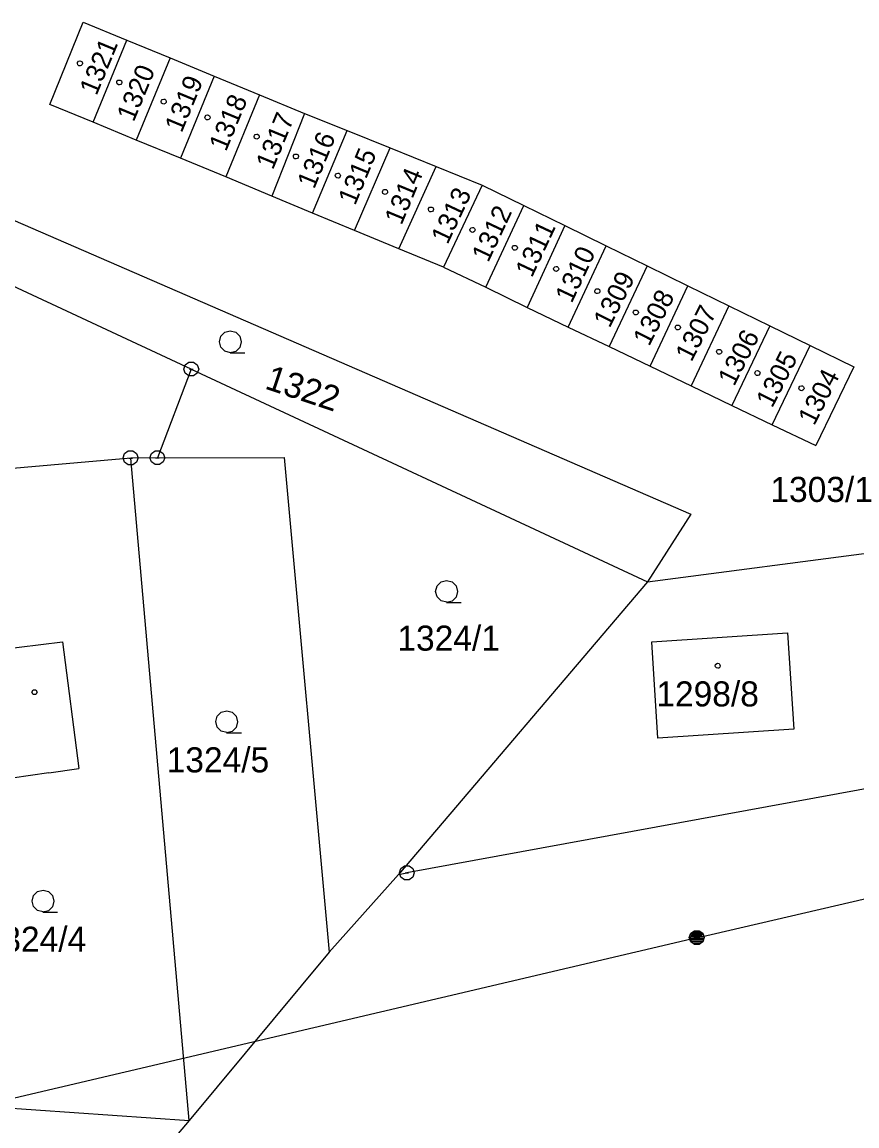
# Model space of a CAD drawing. Extents: x -806774 to -803680, y -1151731 to -1150053.
# Drawn here: x -804567.4 to -804510.8, y -1150464.6 to -1150389.8 of the extents above; entities that cross this region are included whole.
import ezdxf

# ---------------------------------------------------------------- set-up
doc = ezdxf.new("R2010")
doc.units = 0
for name, color, linetype in [('1', 7, 'Continuous'), ('12', 7, 'Continuous'), ('2', 7, 'Continuous'), ('3', 7, 'Continuous'), ('5', 7, 'Continuous'), ('6', 7, 'Continuous'), ('8', 7, 'Continuous')]:
    doc.layers.add(name, color=color, linetype=linetype)

msp = doc.modelspace()

# ---------------------------------------------------------------- linework, layer by layer
at = {"layer": '1'}
for p, q in [((-804565.48, -1150395.39), (-804563.21, -1150389.81)), ((-804563.21, -1150389.81), (-804560.24, -1150391.03)), ((-804562.53, -1150396.6), (-804560.24, -1150391.03)), ((-804560.24, -1150391.03), (-804557.32, -1150392.24)), ((-804557.32, -1150392.24), (-804559.61, -1150397.81)), ((-804557.32, -1150392.24), (-804554.33, -1150393.48)), ((-804554.33, -1150393.48), (-804556.62, -1150399.04)), ((-804554.33, -1150393.48), (-804551.25, -1150394.75)), ((-804562.53, -1150396.6), (-804565.48, -1150395.39)), ((-804551.25, -1150394.75), (-804553.54, -1150400.31)), ((-804551.25, -1150394.75), (-804548.2, -1150396)), ((-804548.2, -1150396), (-804550.43, -1150401.62)), ((-804548.2, -1150396), (-804545.32, -1150397.16)), ((-804559.61, -1150397.81), (-804562.53, -1150396.6)), ((-804547.66, -1150402.76), (-804545.32, -1150397.16)), ((-804545.32, -1150397.16), (-804542.4, -1150398.34)), ((-804556.62, -1150399.04), (-804559.61, -1150397.81)), ((-804544.83, -1150403.93), (-804542.4, -1150398.34)), ((-804542.4, -1150398.34), (-804539.29, -1150399.6)), ((-804553.54, -1150400.31), (-804556.62, -1150399.04)), ((-804541.82, -1150405.18), (-804539.29, -1150399.6)), ((-804539.29, -1150399.6), (-804536.16, -1150400.86)), ((-804574.73, -1150400.29), (-804522.03, -1150423.17)), ((-804550.43, -1150401.62), (-804553.54, -1150400.31)), ((-804536.16, -1150400.86), (-804538.78, -1150406.43)), ((-804536.16, -1150400.86), (-804533.35, -1150402.24)), ((-804547.66, -1150402.76), (-804550.43, -1150401.62)), ((-804544.83, -1150403.93), (-804547.66, -1150402.76)), ((-804535.93, -1150407.79), (-804533.35, -1150402.24)), ((-804533.35, -1150402.24), (-804530.56, -1150403.6)), ((-804530.56, -1150403.6), (-804533.11, -1150409.15)), ((-804530.56, -1150403.6), (-804527.76, -1150404.97)), ((-804555.88, -1150413.34), (-804576.01, -1150403.97)), ((-804541.82, -1150405.18), (-804544.83, -1150403.93)), ((-804538.78, -1150406.43), (-804541.82, -1150405.18)), ((-804530.34, -1150410.48), (-804527.76, -1150404.97)), ((-804527.76, -1150404.97), (-804524.99, -1150406.33)), ((-804538.78, -1150406.43), (-804535.93, -1150407.79)), ((-804524.99, -1150406.33), (-804527.56, -1150411.81)), ((-804524.99, -1150406.33), (-804522.22, -1150407.69)), ((-804535.93, -1150407.79), (-804533.11, -1150409.15)), ((-804524.79, -1150413.14), (-804522.22, -1150407.69)), ((-804522.22, -1150407.69), (-804519.45, -1150409.04)), ((-804533.11, -1150409.15), (-804530.34, -1150410.48)), ((-804519.45, -1150409.04), (-804522.01, -1150414.47)), ((-804519.45, -1150409.04), (-804516.67, -1150410.4)), ((-804516.67, -1150410.4), (-804519.24, -1150415.8)), ((-804516.67, -1150410.4), (-804513.94, -1150411.74)), ((-804530.34, -1150410.48), (-804527.56, -1150411.81)), ((-804527.56, -1150411.81), (-804524.79, -1150413.14)), ((-804516.51, -1150417.1), (-804513.94, -1150411.74)), ((-804513.94, -1150411.74), (-804510.98, -1150413.19)), ((-804555.88, -1150413.34), (-804558.18, -1150419.35)), ((-804555.88, -1150413.34), (-804524.97, -1150427.75)), ((-804524.79, -1150413.14), (-804522.01, -1150414.47)), ((-804510.98, -1150413.19), (-804513.55, -1150418.52)), ((-804522.01, -1150414.47), (-804519.24, -1150415.8)), ((-804519.24, -1150415.8), (-804516.51, -1150417.1)), ((-804516.51, -1150417.1), (-804513.55, -1150418.52)), ((-804559.99, -1150419.36), (-804578.84, -1150421.02)), ((-804558.18, -1150419.35), (-804559.99, -1150419.36)), ((-804556.02, -1150464.26), (-804559.99, -1150419.36)), ((-804558.18, -1150419.35), (-804549.59, -1150419.33)), ((-804549.59, -1150419.33), (-804546.53, -1150452.86)), ((-804522.03, -1150423.17), (-804524.97, -1150427.75)), ((-804524.97, -1150427.75), (-804507.58, -1150425.47)), ((-804524.97, -1150427.75), (-804541.85, -1150447.6)), ((-804524.68, -1150431.81), (-804515.47, -1150431.2)), ((-804515.47, -1150431.2), (-804515.04, -1150437.73)), ((-804569.15, -1150432.37), (-804564.6, -1150431.82)), ((-804564.6, -1150431.82), (-804563.5, -1150440.4)), ((-804457.42, -1150432.08), (-804541.27, -1150447.49)), ((-804524.27, -1150438.36), (-804524.68, -1150431.81)), ((-804515.04, -1150437.73), (-804524.27, -1150438.36)), ((-804565.54, -1150440.7), (-804568.02, -1150441.07)), ((-804565.54, -1150440.7), (-804563.5, -1150440.4)), ((-804541.85, -1150447.6), (-804546.53, -1150452.86)), ((-804541.85, -1150447.6), (-804541.27, -1150447.49)), ((-804546.53, -1150452.86), (-804556.02, -1150464.26)), ((-804575.03, -1150462.95), (-804556.02, -1150464.26)), ((-804556.02, -1150464.26), (-804563.32, -1150472.84))]:
    msp.add_line(p, q, dxfattribs=at)
at = {"layer": '12'}
for p, q in [((-804565.48, -1150395.39), (-804563.21, -1150389.81)), ((-804563.21, -1150389.81), (-804560.24, -1150391.03)), ((-804562.53, -1150396.6), (-804560.24, -1150391.03)), ((-804562.53, -1150396.6), (-804560.24, -1150391.03)), ((-804560.24, -1150391.03), (-804557.32, -1150392.24)), ((-804557.32, -1150392.24), (-804559.61, -1150397.81)), ((-804557.32, -1150392.24), (-804559.61, -1150397.81)), ((-804557.32, -1150392.24), (-804554.33, -1150393.48)), ((-804554.33, -1150393.48), (-804556.62, -1150399.04)), ((-804554.33, -1150393.48), (-804556.62, -1150399.04)), ((-804554.33, -1150393.48), (-804551.25, -1150394.75)), ((-804562.53, -1150396.6), (-804565.48, -1150395.39)), ((-804551.25, -1150394.75), (-804553.54, -1150400.31)), ((-804551.25, -1150394.75), (-804553.54, -1150400.31)), ((-804551.25, -1150394.75), (-804548.2, -1150396)), ((-804548.2, -1150396), (-804550.43, -1150401.62)), ((-804548.2, -1150396), (-804550.43, -1150401.62)), ((-804548.2, -1150396), (-804545.32, -1150397.16)), ((-804559.61, -1150397.81), (-804562.53, -1150396.6)), ((-804547.66, -1150402.76), (-804545.32, -1150397.16)), ((-804547.66, -1150402.76), (-804545.32, -1150397.16)), ((-804545.32, -1150397.16), (-804542.4, -1150398.34)), ((-804556.62, -1150399.04), (-804559.61, -1150397.81)), ((-804544.83, -1150403.93), (-804542.4, -1150398.34)), ((-804544.83, -1150403.93), (-804542.4, -1150398.34)), ((-804542.4, -1150398.34), (-804539.29, -1150399.6)), ((-804553.54, -1150400.31), (-804556.62, -1150399.04)), ((-804541.82, -1150405.18), (-804539.29, -1150399.6)), ((-804541.82, -1150405.18), (-804539.29, -1150399.6)), ((-804539.29, -1150399.6), (-804536.16, -1150400.86)), ((-804550.43, -1150401.62), (-804553.54, -1150400.31)), ((-804536.16, -1150400.86), (-804538.78, -1150406.43)), ((-804536.16, -1150400.86), (-804538.78, -1150406.43)), ((-804536.16, -1150400.86), (-804533.35, -1150402.24)), ((-804547.66, -1150402.76), (-804550.43, -1150401.62)), ((-804544.83, -1150403.93), (-804547.66, -1150402.76)), ((-804535.93, -1150407.79), (-804533.35, -1150402.24)), ((-804535.93, -1150407.79), (-804533.35, -1150402.24)), ((-804533.35, -1150402.24), (-804530.56, -1150403.6)), ((-804530.56, -1150403.6), (-804533.11, -1150409.15)), ((-804530.56, -1150403.6), (-804533.11, -1150409.15)), ((-804530.56, -1150403.6), (-804527.76, -1150404.97)), ((-804541.82, -1150405.18), (-804544.83, -1150403.93)), ((-804538.78, -1150406.43), (-804541.82, -1150405.18)), ((-804530.34, -1150410.48), (-804527.76, -1150404.97)), ((-804530.34, -1150410.48), (-804527.76, -1150404.97)), ((-804527.76, -1150404.97), (-804524.99, -1150406.33)), ((-804538.78, -1150406.43), (-804535.93, -1150407.79)), ((-804524.99, -1150406.33), (-804527.56, -1150411.81)), ((-804524.99, -1150406.33), (-804527.56, -1150411.81)), ((-804524.99, -1150406.33), (-804522.22, -1150407.69)), ((-804535.93, -1150407.79), (-804533.11, -1150409.15)), ((-804524.79, -1150413.14), (-804522.22, -1150407.69)), ((-804524.79, -1150413.14), (-804522.22, -1150407.69)), ((-804522.22, -1150407.69), (-804519.45, -1150409.04)), ((-804533.11, -1150409.15), (-804530.34, -1150410.48)), ((-804519.45, -1150409.04), (-804522.01, -1150414.47)), ((-804519.45, -1150409.04), (-804522.01, -1150414.47)), ((-804519.45, -1150409.04), (-804516.67, -1150410.4)), ((-804516.67, -1150410.4), (-804519.24, -1150415.8)), ((-804516.67, -1150410.4), (-804519.24, -1150415.8)), ((-804516.67, -1150410.4), (-804513.94, -1150411.74)), ((-804530.34, -1150410.48), (-804527.56, -1150411.81)), ((-804527.56, -1150411.81), (-804524.79, -1150413.14)), ((-804516.51, -1150417.1), (-804513.94, -1150411.74)), ((-804516.51, -1150417.1), (-804513.94, -1150411.74)), ((-804513.94, -1150411.74), (-804510.98, -1150413.19)), ((-804524.79, -1150413.14), (-804522.01, -1150414.47)), ((-804510.98, -1150413.19), (-804513.55, -1150418.52)), ((-804522.01, -1150414.47), (-804519.24, -1150415.8)), ((-804519.24, -1150415.8), (-804516.51, -1150417.1)), ((-804516.51, -1150417.1), (-804513.55, -1150418.52)), ((-804524.68, -1150431.81), (-804515.47, -1150431.2)), ((-804515.47, -1150431.2), (-804515.04, -1150437.73)), ((-804524.27, -1150438.36), (-804524.68, -1150431.81)), ((-804515.04, -1150437.73), (-804524.27, -1150438.36))]:
    msp.add_line(p, q, dxfattribs=at)
at = {"layer": '3'}
for points in [[(-804553.23, -1150412.22), (-804553.61, -1150412.12), (-804553.88, -1150411.85), (-804553.98, -1150411.48), (-804553.88, -1150411.11), (-804553.61, -1150410.84), (-804553.24, -1150410.74), (-804552.87, -1150410.84), (-804552.6, -1150411.11), (-804552.5, -1150411.49), (-804552.6, -1150411.87), (-804552.87, -1150412.14), (-804553.25, -1150412.24), (-804552.25, -1150412.24)], [(-804538.57, -1150429.14), (-804538.95, -1150429.04), (-804539.22, -1150428.77), (-804539.32, -1150428.4), (-804539.22, -1150428.03), (-804538.95, -1150427.76), (-804538.58, -1150427.66), (-804538.21, -1150427.76), (-804537.94, -1150428.03), (-804537.84, -1150428.41), (-804537.94, -1150428.79), (-804538.21, -1150429.06), (-804538.59, -1150429.16), (-804537.59, -1150429.16)], [(-804553.47, -1150437.97), (-804553.85, -1150437.87), (-804554.12, -1150437.6), (-804554.22, -1150437.23), (-804554.12, -1150436.86), (-804553.85, -1150436.59), (-804553.48, -1150436.49), (-804553.11, -1150436.59), (-804552.84, -1150436.86), (-804552.74, -1150437.24), (-804552.84, -1150437.62), (-804553.11, -1150437.89), (-804553.49, -1150437.99), (-804552.49, -1150437.99)], [(-804565.92, -1150450.13), (-804566.3, -1150450.03), (-804566.57, -1150449.76), (-804566.67, -1150449.39), (-804566.57, -1150449.02), (-804566.3, -1150448.75), (-804565.93, -1150448.65), (-804565.56, -1150448.75), (-804565.29, -1150449.02), (-804565.19, -1150449.4), (-804565.29, -1150449.78), (-804565.56, -1150450.05), (-804565.94, -1150450.15), (-804564.94, -1150450.15)]]:
    msp.add_lwpolyline(points, dxfattribs=at)
at = {"layer": '5'}
for points in [[(-804563.587, -1150392.545), (-804563.53, -1150392.46), (-804563.428, -1150392.448), (-804563.365, -1150392.453), (-804563.289, -1150392.506), (-804563.255, -1150392.607), (-804563.273, -1150392.675), (-804563.335, -1150392.747), (-804563.414, -1150392.779), (-804563.495, -1150392.767), (-804563.571, -1150392.714), (-804563.605, -1150392.613)], [(-804560.917, -1150393.835), (-804560.86, -1150393.75), (-804560.758, -1150393.738), (-804560.695, -1150393.743), (-804560.619, -1150393.796), (-804560.585, -1150393.897), (-804560.603, -1150393.965), (-804560.665, -1150394.037), (-804560.744, -1150394.069), (-804560.825, -1150394.057), (-804560.901, -1150394.004), (-804560.935, -1150393.903)], [(-804557.907, -1150395.135), (-804557.85, -1150395.05), (-804557.748, -1150395.038), (-804557.685, -1150395.043), (-804557.609, -1150395.096), (-804557.575, -1150395.197), (-804557.593, -1150395.265), (-804557.655, -1150395.337), (-804557.734, -1150395.369), (-804557.815, -1150395.357), (-804557.891, -1150395.304), (-804557.925, -1150395.203)], [(-804554.937, -1150396.205), (-804554.88, -1150396.12), (-804554.778, -1150396.108), (-804554.715, -1150396.113), (-804554.639, -1150396.166), (-804554.605, -1150396.267), (-804554.623, -1150396.335), (-804554.685, -1150396.407), (-804554.764, -1150396.439), (-804554.845, -1150396.427), (-804554.921, -1150396.374), (-804554.955, -1150396.273)], [(-804551.607, -1150397.505), (-804551.55, -1150397.42), (-804551.448, -1150397.408), (-804551.385, -1150397.413), (-804551.309, -1150397.466), (-804551.275, -1150397.567), (-804551.293, -1150397.635), (-804551.355, -1150397.707), (-804551.434, -1150397.739), (-804551.515, -1150397.727), (-804551.591, -1150397.674), (-804551.625, -1150397.573)], [(-804548.947, -1150398.855), (-804548.89, -1150398.77), (-804548.788, -1150398.758), (-804548.725, -1150398.763), (-804548.649, -1150398.816), (-804548.615, -1150398.917), (-804548.633, -1150398.985), (-804548.695, -1150399.057), (-804548.774, -1150399.089), (-804548.855, -1150399.077), (-804548.931, -1150399.024), (-804548.965, -1150398.923)], [(-804546.107, -1150400.155), (-804546.05, -1150400.07), (-804545.948, -1150400.058), (-804545.885, -1150400.063), (-804545.809, -1150400.116), (-804545.775, -1150400.217), (-804545.793, -1150400.285), (-804545.855, -1150400.357), (-804545.934, -1150400.389), (-804546.015, -1150400.377), (-804546.091, -1150400.324), (-804546.125, -1150400.223)], [(-804542.907, -1150401.255), (-804542.85, -1150401.17), (-804542.748, -1150401.158), (-804542.685, -1150401.163), (-804542.609, -1150401.216), (-804542.575, -1150401.317), (-804542.593, -1150401.385), (-804542.655, -1150401.457), (-804542.734, -1150401.489), (-804542.815, -1150401.477), (-804542.891, -1150401.424), (-804542.925, -1150401.323)], [(-804539.797, -1150402.445), (-804539.74, -1150402.36), (-804539.638, -1150402.348), (-804539.575, -1150402.353), (-804539.499, -1150402.406), (-804539.465, -1150402.507), (-804539.483, -1150402.575), (-804539.545, -1150402.647), (-804539.624, -1150402.679), (-804539.705, -1150402.667), (-804539.781, -1150402.614), (-804539.815, -1150402.513)], [(-804536.977, -1150403.835), (-804536.92, -1150403.75), (-804536.818, -1150403.738), (-804536.755, -1150403.743), (-804536.679, -1150403.796), (-804536.645, -1150403.897), (-804536.663, -1150403.965), (-804536.725, -1150404.037), (-804536.804, -1150404.069), (-804536.885, -1150404.057), (-804536.961, -1150404.004), (-804536.995, -1150403.903)], [(-804534.107, -1150405.045), (-804534.05, -1150404.96), (-804533.948, -1150404.948), (-804533.885, -1150404.953), (-804533.809, -1150405.006), (-804533.775, -1150405.107), (-804533.793, -1150405.175), (-804533.855, -1150405.247), (-804533.934, -1150405.279), (-804534.015, -1150405.267), (-804534.091, -1150405.214), (-804534.125, -1150405.113)], [(-804531.307, -1150406.475), (-804531.25, -1150406.39), (-804531.148, -1150406.378), (-804531.085, -1150406.383), (-804531.009, -1150406.436), (-804530.975, -1150406.537), (-804530.993, -1150406.605), (-804531.055, -1150406.677), (-804531.134, -1150406.709), (-804531.215, -1150406.697), (-804531.291, -1150406.644), (-804531.325, -1150406.543)], [(-804528.517, -1150407.985), (-804528.46, -1150407.9), (-804528.358, -1150407.888), (-804528.295, -1150407.893), (-804528.219, -1150407.946), (-804528.185, -1150408.047), (-804528.203, -1150408.115), (-804528.265, -1150408.187), (-804528.344, -1150408.219), (-804528.425, -1150408.207), (-804528.501, -1150408.154), (-804528.535, -1150408.053)], [(-804525.907, -1150409.425), (-804525.85, -1150409.34), (-804525.748, -1150409.328), (-804525.685, -1150409.333), (-804525.609, -1150409.386), (-804525.575, -1150409.487), (-804525.593, -1150409.555), (-804525.655, -1150409.627), (-804525.734, -1150409.659), (-804525.815, -1150409.647), (-804525.891, -1150409.594), (-804525.925, -1150409.493)], [(-804523.067, -1150410.445), (-804523.01, -1150410.36), (-804522.908, -1150410.348), (-804522.845, -1150410.353), (-804522.769, -1150410.406), (-804522.735, -1150410.507), (-804522.753, -1150410.575), (-804522.815, -1150410.647), (-804522.894, -1150410.679), (-804522.975, -1150410.667), (-804523.051, -1150410.614), (-804523.085, -1150410.513)], [(-804520.267, -1150412.095), (-804520.21, -1150412.01), (-804520.108, -1150411.998), (-804520.045, -1150412.003), (-804519.969, -1150412.056), (-804519.935, -1150412.157), (-804519.953, -1150412.225), (-804520.015, -1150412.297), (-804520.094, -1150412.329), (-804520.175, -1150412.317), (-804520.251, -1150412.264), (-804520.285, -1150412.163)], [(-804517.667, -1150413.535), (-804517.61, -1150413.45), (-804517.508, -1150413.438), (-804517.445, -1150413.443), (-804517.369, -1150413.496), (-804517.335, -1150413.597), (-804517.353, -1150413.665), (-804517.415, -1150413.737), (-804517.494, -1150413.769), (-804517.575, -1150413.757), (-804517.651, -1150413.704), (-804517.685, -1150413.603)], [(-804514.687, -1150414.565), (-804514.63, -1150414.48), (-804514.528, -1150414.468), (-804514.465, -1150414.473), (-804514.389, -1150414.526), (-804514.355, -1150414.627), (-804514.373, -1150414.695), (-804514.435, -1150414.767), (-804514.514, -1150414.799), (-804514.595, -1150414.787), (-804514.671, -1150414.734), (-804514.705, -1150414.633)], [(-804520.2, -1150433.27), (-804520.1, -1150433.29), (-804520.05, -1150433.38), (-804520.03, -1150433.44), (-804520.05, -1150433.53), (-804520.13, -1150433.6), (-804520.2, -1150433.61), (-804520.29, -1150433.58), (-804520.35, -1150433.52), (-804520.37, -1150433.44), (-804520.35, -1150433.35), (-804520.27, -1150433.28)], [(-804566.41, -1150435.08), (-804566.32, -1150435.23), (-804566.41, -1150435.38), (-804566.59, -1150435.38), (-804566.68, -1150435.23), (-804566.59, -1150435.08)]]:
    msp.add_lwpolyline(points, close=True, dxfattribs=at)
at = {"layer": '6'}
for q in [(-804453.4, -1150436.09), (-804579.51, -1150465.49)]:
    msp.add_line((-804521.63, -1150451.88), q, dxfattribs=at)
msp.add_lwpolyline([(-804521.78, -1150451.4), (-804521.47, -1150451.4), (-804521.22, -1150451.58), (-804521.12, -1150451.87), (-804521.22, -1150452.16), (-804521.47, -1150452.34), (-804521.78, -1150452.34), (-804522.03, -1150452.16), (-804522.13, -1150451.87), (-804522.03, -1150451.58), (-804521.78, -1150451.4), (-804521.75, -1150451.44), (-804521.51, -1150451.44), (-804521.35, -1150451.52), (-804521.91, -1150451.52), (-804521.99, -1150451.6), (-804521.27, -1150451.6), (-804521.27, -1150451.68), (-804521.99, -1150451.68), (-804522.03, -1150451.76), (-804521.23, -1150451.76), (-804521.19, -1150451.84), (-804522.07, -1150451.84), (-804522.07, -1150451.92), (-804521.19, -1150451.92), (-804521.22, -1150452), (-804522.03, -1150452), (-804522.02, -1150452.08), (-804521.21, -1150452.08), (-804521.26, -1150452.16), (-804521.98, -1150452.16), (-804521.9, -1150452.24), (-804521.34, -1150452.24), (-804521.45, -1150452.32), (-804521.79, -1150452.32)], dxfattribs=at)
at = {"layer": '8'}
for p, q in [((-804556, -1150413.34), (-804555.76, -1150413.34)), ((-804560.11, -1150419.36), (-804559.87, -1150419.36)), ((-804558.3, -1150419.35), (-804558.06, -1150419.35)), ((-804541.39, -1150447.49), (-804541.15, -1150447.49))]:
    msp.add_line(p, q, dxfattribs=at)
for points in [[(-804555.73, -1150412.86), (-804555.48, -1150413.04), (-804555.38, -1150413.33), (-804555.48, -1150413.62), (-804555.73, -1150413.8), (-804556.04, -1150413.8), (-804556.29, -1150413.62), (-804556.39, -1150413.33), (-804556.29, -1150413.04), (-804556.04, -1150412.86)], [(-804559.84, -1150418.88), (-804559.59, -1150419.06), (-804559.49, -1150419.35), (-804559.59, -1150419.64), (-804559.84, -1150419.82), (-804560.15, -1150419.82), (-804560.4, -1150419.64), (-804560.5, -1150419.35), (-804560.4, -1150419.06), (-804560.15, -1150418.88)], [(-804558.03, -1150418.87), (-804557.78, -1150419.05), (-804557.68, -1150419.34), (-804557.78, -1150419.63), (-804558.03, -1150419.81), (-804558.34, -1150419.81), (-804558.59, -1150419.63), (-804558.69, -1150419.34), (-804558.59, -1150419.05), (-804558.34, -1150418.87)], [(-804541.12, -1150447.01), (-804540.87, -1150447.19), (-804540.77, -1150447.48), (-804540.87, -1150447.77), (-804541.12, -1150447.95), (-804541.43, -1150447.95), (-804541.68, -1150447.77), (-804541.78, -1150447.48), (-804541.68, -1150447.19), (-804541.43, -1150447.01)]]:
    msp.add_lwpolyline(points, close=True, dxfattribs=at)

# ---------------------------------------------------------------- texts
at = {"layer": '2'}
for s, height, rotation, p in [('1321', 1.3, 67.49443, (-804562.307, -1150394.848)), ('1320', 1.3, 67.49443, (-804559.786, -1150396.633)), ('1319', 1.3, 67.49443, (-804556.535, -1150397.366)), ('1318', 1.3, 67.49443, (-804553.531, -1150398.64)), ('1317', 1.3, 67.49443, (-804550.353, -1150399.878)), ('1316', 1.3, 67.49443, (-804547.555, -1150401.176)), ('1315', 1.3, 67.49443, (-804544.779, -1150402.289)), ('1314', 1.3, 67.49443, (-804541.635, -1150403.626)), ('1313', 1.3, 64.80153, (-804538.513, -1150404.935)), ('1312', 1.3, 64.80153, (-804535.758, -1150406.155)), ('1311', 1.3, 64.80153, (-804532.801, -1150407.184)), ('1310', 1.3, 64.80153, (-804530.103, -1150408.923)), ('1309', 1.3, 63.02536, (-804527.536, -1150410.597)), ('1308', 1.3, 63.02536, (-804524.853, -1150411.84)), ('1307', 1.3, 63.02536, (-804521.982, -1150412.899)), ('1306', 1.3, 63.02536, (-804519.096, -1150414.547)), ('1305', 1.3, 63.02536, (-804516.513, -1150416.019)), ('1322', 1.7, 341.54014, (-804550.969, -1150414.635)), ('1304', 1.3, 63.02536, (-804513.666, -1150417.217))]:
    msp.add_text(s, height=height, rotation=rotation, dxfattribs=at).set_placement(p)
for s, p in [('1303/1', (-804516.635, -1150422.338)), ('1324/1', (-804541.917, -1150432.42)), ('1298/8', (-804524.365, -1150436.2)), ('1324/5', (-804557.552, -1150440.67)), ('1324/4', (-804569.955, -1150452.83))]:
    msp.add_text(s, height=1.7, dxfattribs=at).set_placement(p)

doc.saveas('drawing.dxf')
